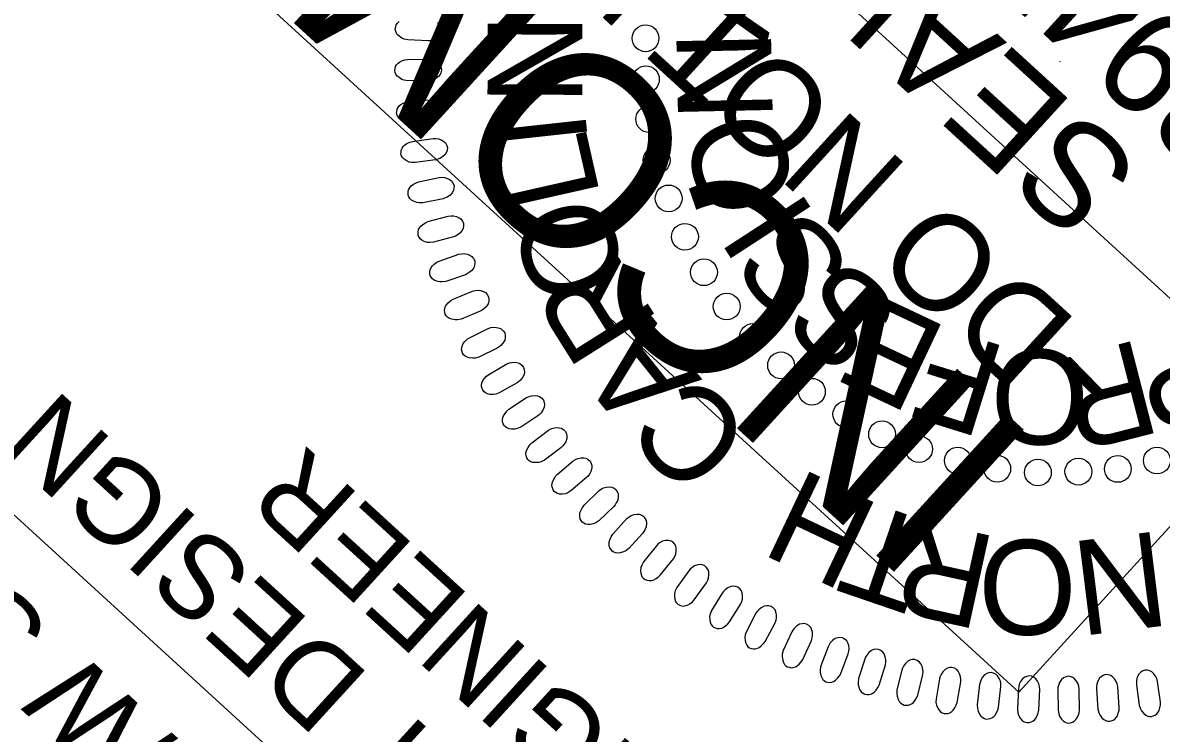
# Model space of a CAD drawing. Extents: x 475722 to 477703, y 499689 to 501633.
# Drawn here: x 475865.2 to 475933.3, y 500762.6 to 500805.1 of the extents above; entities that cross this region are included whole.
import ezdxf

# ---------------------------------------------------------------- set-up
doc = ezdxf.new("R2010")
doc.units = 0
for name, color, linetype in [('Sheet Data Field CELL', 7, 'Continuous'), ('Sheet PE Seal Cell', 7, 'Continuous'), ('Sheet Plan CELL', 7, 'Continuous'), ('Sheet Sticker Incomplete CELL', 7, 'Continuous')]:
    doc.layers.add(name, color=color, linetype=linetype)

msp = doc.modelspace()

# ---------------------------------------------------------------- linework, layer by layer
at = {"layer": 'Sheet PE Seal Cell'}
msp.add_line((475927.242, 500802.785), (475927.274, 500802.82), dxfattribs=at)
msp.add_lwpolyline([(475889.983, 500805.132), (475890.117, 500805.013), (475890.192, 500804.912), (475890.244, 500804.752), (475890.256, 500804.601), (475890.209, 500804.455), (475890.154, 500804.352), (475890.048, 500804.23), (475889.873, 500804.119), (475889.69, 500804.061), (475889.559, 500804.038), (475889.429, 500804.029), (475888.204, 500804.09), (475887.986, 500804.138), (475887.849, 500804.197), (475887.686, 500804.317), (475887.581, 500804.42), (475887.507, 500804.536), (475887.472, 500804.642), (475887.458, 500804.756), (475887.483, 500804.867), (475887.519, 500804.985), (475887.584, 500805.086), (475887.689, 500805.186)], dxfattribs=at)
for points in [[(475889.441, 500801.652), (475888.214, 500801.636), (475887.995, 500801.671), (475887.854, 500801.721), (475887.683, 500801.831), (475887.572, 500801.926), (475887.491, 500802.037), (475887.45, 500802.142), (475887.428, 500802.254), (475887.447, 500802.366), (475887.475, 500802.486), (475887.533, 500802.592), (475887.632, 500802.698), (475887.711, 500802.758), (475887.86, 500802.827), (475888.038, 500802.89), (475888.197, 500802.915), (475889.454, 500802.938), (475889.624, 500802.918), (475889.764, 500802.875), (475889.924, 500802.788), (475890.066, 500802.677), (475890.147, 500802.581), (475890.209, 500802.425), (475890.231, 500802.276), (475890.193, 500802.126), (475890.144, 500802.021), (475890.046, 500801.892), (475889.878, 500801.77), (475889.699, 500801.701), (475889.57, 500801.669)], [(475889.587, 500799.226), (475888.363, 500799.133), (475888.142, 500799.153), (475887.998, 500799.194), (475887.821, 500799.293), (475887.704, 500799.382), (475887.616, 500799.487), (475887.568, 500799.589), (475887.54, 500799.699), (475887.551, 500799.812), (475887.572, 500799.934), (475887.623, 500800.043), (475887.715, 500800.155), (475887.79, 500800.221), (475887.934, 500800.299), (475888.109, 500800.372), (475888.266, 500800.407), (475889.518, 500800.51), (475889.689, 500800.5), (475889.832, 500800.466), (475889.997, 500800.389), (475890.145, 500800.288), (475890.232, 500800.197), (475890.304, 500800.045), (475890.335, 500799.897), (475890.306, 500799.745), (475890.265, 500799.637), (475890.175, 500799.503), (475890.015, 500799.371), (475889.842, 500799.29), (475889.714, 500799.251)], [(475889.873, 500796.913), (475888.658, 500796.743), (475888.436, 500796.749), (475888.29, 500796.782), (475888.106, 500796.869), (475887.985, 500796.95), (475887.89, 500797.051), (475887.836, 500797.148), (475887.801, 500797.257), (475887.805, 500797.37), (475887.818, 500797.493), (475887.863, 500797.605), (475887.947, 500797.723), (475888.018, 500797.793), (475888.157, 500797.88), (475888.326, 500797.964), (475888.481, 500798.009), (475889.724, 500798.19), (475889.896, 500798.192), (475890.04, 500798.166), (475890.21, 500798.1), (475890.365, 500798.008), (475890.457, 500797.923), (475890.538, 500797.776), (475890.578, 500797.63), (475890.56, 500797.477), (475890.525, 500797.366), (475890.443, 500797.227), (475890.292, 500797.085), (475890.123, 500796.993), (475889.999, 500796.946)], [(475890.316, 500794.589), (475889.115, 500794.344), (475888.892, 500794.336), (475888.744, 500794.359), (475888.556, 500794.435), (475888.429, 500794.508), (475888.329, 500794.602), (475888.268, 500794.697), (475888.226, 500794.803), (475888.223, 500794.916), (475888.229, 500795.039), (475888.266, 500795.154), (475888.343, 500795.277), (475888.409, 500795.352), (475888.542, 500795.448), (475888.706, 500795.542), (475888.858, 500795.596), (475890.088, 500795.855), (475890.258, 500795.867), (475890.404, 500795.851), (475890.578, 500795.795), (475890.738, 500795.713), (475890.836, 500795.634), (475890.925, 500795.492), (475890.975, 500795.35), (475890.966, 500795.195), (475890.938, 500795.083), (475890.866, 500794.938), (475890.723, 500794.787), (475890.561, 500794.685), (475890.44, 500794.63)], [(475890.934, 500792.301), (475889.75, 500791.98), (475889.528, 500791.958), (475889.38, 500791.972), (475889.187, 500792.036), (475889.055, 500792.101), (475888.949, 500792.189), (475888.884, 500792.279), (475888.835, 500792.383), (475888.825, 500792.496), (475888.823, 500792.619), (475888.852, 500792.736), (475888.922, 500792.863), (475888.983, 500792.941), (475889.11, 500793.046), (475889.267, 500793.15), (475889.415, 500793.214), (475890.626, 500793.549), (475890.796, 500793.572), (475890.942, 500793.565), (475891.12, 500793.52), (475891.284, 500793.449), (475891.387, 500793.376), (475891.486, 500793.24), (475891.543, 500793.101), (475891.544, 500792.946), (475891.523, 500792.832), (475891.461, 500792.683), (475891.328, 500792.524), (475891.172, 500792.412), (475891.055, 500792.349)], [(475891.654, 500790.037), (475890.492, 500789.643), (475890.273, 500789.608), (475890.124, 500789.612), (475889.927, 500789.664), (475889.792, 500789.721), (475889.68, 500789.801), (475889.609, 500789.888), (475889.554, 500789.987), (475889.537, 500790.1), (475889.527, 500790.223), (475889.549, 500790.341), (475889.61, 500790.472), (475889.667, 500790.554), (475889.786, 500790.666), (475889.937, 500790.781), (475890.081, 500790.854), (475891.269, 500791.264), (475891.436, 500791.298), (475891.583, 500791.3), (475891.763, 500791.267), (475891.931, 500791.205), (475892.038, 500791.139), (475892.145, 500791.01), (475892.212, 500790.875), (475892.223, 500790.72), (475892.209, 500790.605), (475892.155, 500790.452), (475892.033, 500790.285), (475891.885, 500790.163), (475891.771, 500790.093)], [(475892.537, 500787.855), (475891.402, 500787.389), (475891.185, 500787.34), (475891.036, 500787.335), (475890.837, 500787.374), (475890.698, 500787.422), (475890.582, 500787.496), (475890.505, 500787.577), (475890.444, 500787.673), (475890.42, 500787.785), (475890.402, 500787.906), (475890.417, 500788.026), (475890.47, 500788.161), (475890.521, 500788.246), (475890.634, 500788.366), (475890.777, 500788.489), (475890.916, 500788.571), (475892.075, 500789.056), (475892.24, 500789.099), (475892.387, 500789.111), (475892.569, 500789.089), (475892.74, 500789.038), (475892.852, 500788.979), (475892.967, 500788.856), (475893.041, 500788.725), (475893.061, 500788.572), (475893.055, 500788.457), (475893.011, 500788.301), (475892.9, 500788.126), (475892.76, 500787.995), (475892.651, 500787.919)], [(475893.561, 500785.654), (475892.459, 500785.117), (475892.245, 500785.055), (475892.096, 500785.04), (475891.895, 500785.067), (475891.753, 500785.106), (475891.633, 500785.172), (475891.551, 500785.249), (475891.484, 500785.341), (475891.453, 500785.45), (475891.428, 500785.571), (475891.436, 500785.691), (475891.479, 500785.829), (475891.525, 500785.918), (475891.63, 500786.044), (475891.765, 500786.176), (475891.899, 500786.266), (475893.025, 500786.823), (475893.188, 500786.877), (475893.333, 500786.898), (475893.515, 500786.887), (475893.69, 500786.848), (475893.804, 500786.795), (475893.927, 500786.679), (475894.01, 500786.554), (475894.04, 500786.402), (475894.041, 500786.286), (475894.007, 500786.128), (475893.906, 500785.947), (475893.775, 500785.807), (475893.671, 500785.724)], [(475894.751, 500783.571), (475893.684, 500782.966), (475893.474, 500782.89), (475893.328, 500782.867), (475893.124, 500782.88), (475892.981, 500782.911), (475892.857, 500782.969), (475892.77, 500783.04), (475892.698, 500783.128), (475892.66, 500783.236), (475892.627, 500783.355), (475892.627, 500783.475), (475892.662, 500783.615), (475892.702, 500783.706), (475892.799, 500783.839), (475892.926, 500783.979), (475893.053, 500784.078), (475894.143, 500784.704), (475894.301, 500784.769), (475894.445, 500784.798), (475894.628, 500784.799), (475894.805, 500784.77), (475894.922, 500784.725), (475895.052, 500784.618), (475895.143, 500784.497), (475895.182, 500784.348), (475895.19, 500784.233), (475895.166, 500784.073), (475895.078, 500783.885), (475894.955, 500783.738), (475894.856, 500783.648)], [(475895.992, 500781.594), (475894.966, 500780.923), (475894.762, 500780.834), (475894.616, 500780.802), (475894.412, 500780.803), (475894.268, 500780.824), (475894.14, 500780.874), (475894.049, 500780.94), (475893.97, 500781.023), (475893.926, 500781.128), (475893.886, 500781.244), (475893.879, 500781.365), (475893.905, 500781.506), (475893.939, 500781.6), (475894.028, 500781.739), (475894.145, 500781.887), (475894.266, 500781.994), (475895.315, 500782.687), (475895.469, 500782.76), (475895.61, 500782.799), (475895.792, 500782.811), (475895.971, 500782.794), (475896.091, 500782.757), (475896.227, 500782.658), (475896.325, 500782.543), (475896.373, 500782.396), (475896.389, 500782.282), (475896.375, 500782.121), (475896.299, 500781.928), (475896.185, 500781.773), (475896.093, 500781.678)], [(475897.375, 500779.689), (475896.392, 500778.955), (475896.194, 500778.854), (475896.051, 500778.812), (475895.848, 500778.801), (475895.702, 500778.813), (475895.571, 500778.855), (475895.476, 500778.915), (475895.393, 500778.993), (475895.342, 500779.094), (475895.294, 500779.208), (475895.28, 500779.328), (475895.297, 500779.471), (475895.325, 500779.567), (475895.405, 500779.71), (475895.512, 500779.866), (475895.627, 500779.98), (475896.629, 500780.738), (475896.779, 500780.82), (475896.917, 500780.868), (475897.099, 500780.892), (475897.278, 500780.886), (475897.4, 500780.856), (475897.542, 500780.766), (475897.647, 500780.658), (475897.705, 500780.514), (475897.727, 500780.401), (475897.723, 500780.239), (475897.659, 500780.042), (475897.556, 500779.881), (475897.469, 500779.779)], [(475898.908, 500777.9), (475897.974, 500777.105), (475897.782, 500776.991), (475897.642, 500776.941), (475897.44, 500776.917), (475897.293, 500776.92), (475897.16, 500776.954), (475897.062, 500777.007), (475896.974, 500777.08), (475896.917, 500777.179), (475896.863, 500777.289), (475896.84, 500777.407), (475896.849, 500777.552), (475896.87, 500777.649), (475896.941, 500777.798), (475897.039, 500777.959), (475897.146, 500778.079), (475898.099, 500778.899), (475898.243, 500778.991), (475898.377, 500779.048), (475898.557, 500779.083), (475898.736, 500779.088), (475898.86, 500779.066), (475899.007, 500778.984), (475899.12, 500778.884), (475899.186, 500778.744), (475899.216, 500778.632), (475899.222, 500778.47), (475899.17, 500778.269), (475899.077, 500778.102), (475898.997, 500777.995)], [(475900.534, 500776.177), (475899.651, 500775.325), (475899.468, 500775.199), (475899.331, 500775.141), (475899.131, 500775.104), (475898.984, 500775.097), (475898.849, 500775.123), (475898.748, 500775.171), (475898.655, 500775.238), (475898.592, 500775.332), (475898.531, 500775.439), (475898.501, 500775.556), (475898.5, 500775.7), (475898.516, 500775.798), (475898.577, 500775.951), (475898.665, 500776.118), (475898.763, 500776.245), (475899.664, 500777.123), (475899.801, 500777.225), (475899.933, 500777.289), (475900.11, 500777.335), (475900.288, 500777.352), (475900.413, 500777.337), (475900.565, 500777.266), (475900.683, 500777.172), (475900.758, 500777.037), (475900.795, 500776.926), (475900.811, 500776.766), (475900.772, 500776.562), (475900.69, 500776.389), (475900.617, 500776.277)], [(475902.258, 500774.566), (475901.43, 500773.661), (475901.255, 500773.524), (475901.121, 500773.456), (475900.925, 500773.407), (475900.779, 500773.391), (475900.642, 500773.408), (475900.538, 500773.449), (475900.442, 500773.51), (475900.373, 500773.601), (475900.304, 500773.703), (475900.268, 500773.818), (475900.258, 500773.962), (475900.268, 500774.062), (475900.319, 500774.217), (475900.396, 500774.391), (475900.487, 500774.523), (475901.329, 500775.455), (475901.46, 500775.566), (475901.588, 500775.638), (475901.761, 500775.695), (475901.939, 500775.723), (475902.064, 500775.716), (475902.22, 500775.654), (475902.344, 500775.568), (475902.427, 500775.438), (475902.471, 500775.331), (475902.498, 500775.171), (475902.471, 500774.965), (475902.4, 500774.787), (475902.334, 500774.672)], [(475903.087, 500773.82), (475902.318, 500772.865), (475902.21, 500772.67), (475902.163, 500772.529), (475902.144, 500772.326), (475902.151, 500772.18), (475902.188, 500772.047), (475902.244, 500771.951), (475902.32, 500771.865), (475902.419, 500771.81), (475902.531, 500771.759), (475902.65, 500771.739), (475902.794, 500771.752), (475902.891, 500771.776), (475903.037, 500771.85), (475903.196, 500771.953), (475903.313, 500772.063), (475904.107, 500773.037), (475904.196, 500773.183), (475904.249, 500773.32), (475904.28, 500773.501), (475904.279, 500773.68), (475904.254, 500773.803), (475904.169, 500773.948), (475904.065, 500774.057), (475903.923, 500774.12), (475903.811, 500774.147), (475903.649, 500774.148), (475903.45, 500774.092), (475903.285, 500773.994), (475903.18, 500773.912)], [(475905.024, 500772.325), (475904.316, 500771.323), (475904.22, 500771.122), (475904.182, 500770.978), (475904.176, 500770.775), (475904.192, 500770.629), (475904.238, 500770.5), (475904.3, 500770.406), (475904.38, 500770.325), (475904.484, 500770.277), (475904.598, 500770.233), (475904.718, 500770.221), (475904.861, 500770.242), (475904.956, 500770.273), (475905.098, 500770.356), (475905.25, 500770.468), (475905.36, 500770.585), (475906.091, 500771.608), (475906.171, 500771.759), (475906.215, 500771.899), (475906.234, 500772.081), (475906.223, 500772.26), (475906.189, 500772.381), (475906.096, 500772.521), (475905.985, 500772.623), (475905.84, 500772.677), (475905.726, 500772.696), (475905.564, 500772.688), (475905.369, 500772.619), (475905.211, 500772.511), (475905.112, 500772.422)], [(475907.03, 500770.99), (475906.387, 500769.947), (475906.304, 500769.74), (475906.274, 500769.593), (475906.281, 500769.39), (475906.306, 500769.246), (475906.36, 500769.119), (475906.428, 500769.031), (475906.513, 500768.954), (475906.619, 500768.913), (475906.737, 500768.876), (475906.857, 500768.871), (475906.999, 500768.901), (475907.092, 500768.938), (475907.227, 500769.03), (475907.372, 500769.151), (475907.475, 500769.276), (475908.14, 500770.342), (475908.21, 500770.498), (475908.246, 500770.64), (475908.253, 500770.823), (475908.23, 500771.001), (475908.19, 500771.12), (475908.087, 500771.253), (475907.97, 500771.348), (475907.822, 500771.393), (475907.707, 500771.405), (475907.547, 500771.387), (475907.356, 500771.306), (475907.204, 500771.188), (475907.111, 500771.093)], [(475909.051, 500769.784), (475908.474, 500768.701), (475908.404, 500768.49), (475908.384, 500768.342), (475908.404, 500768.14), (475908.438, 500767.998), (475908.499, 500767.874), (475908.573, 500767.789), (475908.662, 500767.719), (475908.771, 500767.684), (475908.89, 500767.655), (475909.011, 500767.658), (475909.15, 500767.697), (475909.24, 500767.739), (475909.37, 500767.84), (475909.507, 500767.97), (475909.602, 500768.1), (475910.199, 500769.206), (475910.259, 500769.366), (475910.285, 500769.51), (475910.281, 500769.693), (475910.248, 500769.869), (475910.199, 500769.985), (475910.089, 500770.113), (475909.966, 500770.2), (475909.816, 500770.235), (475909.7, 500770.241), (475909.541, 500770.212), (475909.356, 500770.118), (475909.212, 500769.992), (475909.125, 500769.892)], [(475911.192, 500768.668), (475910.685, 500767.551), (475910.627, 500767.336), (475910.617, 500767.188), (475910.649, 500766.987), (475910.692, 500766.846), (475910.761, 500766.728), (475910.84, 500766.648), (475910.934, 500766.583), (475911.044, 500766.554), (475911.165, 500766.533), (475911.285, 500766.544), (475911.422, 500766.591), (475911.51, 500766.639), (475911.633, 500766.748), (475911.762, 500766.886), (475911.848, 500767.023), (475912.375, 500768.163), (475912.424, 500768.327), (475912.441, 500768.472), (475912.426, 500768.655), (475912.381, 500768.828), (475912.326, 500768.941), (475912.208, 500769.061), (475912.08, 500769.141), (475911.927, 500769.166), (475911.811, 500769.164), (475911.654, 500769.126), (475911.475, 500769.021), (475911.34, 500768.885), (475911.259, 500768.78)], [(475913.367, 500767.786), (475912.931, 500766.639), (475912.888, 500766.421), (475912.887, 500766.272), (475912.931, 500766.074), (475912.983, 500765.937), (475913.06, 500765.822), (475913.143, 500765.748), (475913.241, 500765.69), (475913.353, 500765.668), (475913.475, 500765.653), (475913.594, 500765.672), (475913.728, 500765.728), (475913.812, 500765.781), (475913.928, 500765.897), (475914.048, 500766.044), (475914.125, 500766.185), (475914.579, 500767.357), (475914.619, 500767.523), (475914.626, 500767.669), (475914.6, 500767.851), (475914.545, 500768.021), (475914.482, 500768.13), (475914.357, 500768.242), (475914.224, 500768.314), (475914.07, 500768.329), (475913.955, 500768.32), (475913.8, 500768.272), (475913.628, 500768.157), (475913.501, 500768.012), (475913.427, 500767.902)], [(475915.56, 500767.046), (475915.196, 500765.875), (475915.167, 500765.655), (475915.175, 500765.505), (475915.231, 500765.31), (475915.293, 500765.177), (475915.376, 500765.067), (475915.464, 500764.998), (475915.565, 500764.946), (475915.678, 500764.932), (475915.801, 500764.925), (475915.919, 500764.951), (475916.049, 500765.015), (475916.129, 500765.074), (475916.238, 500765.196), (475916.348, 500765.35), (475916.417, 500765.496), (475916.796, 500766.694), (475916.825, 500766.863), (475916.824, 500767.009), (475916.785, 500767.188), (475916.719, 500767.355), (475916.651, 500767.459), (475916.518, 500767.563), (475916.381, 500767.627), (475916.227, 500767.633), (475916.112, 500767.616), (475915.961, 500767.559), (475915.797, 500767.433), (475915.679, 500767.281), (475915.612, 500767.166)], [(475917.782, 500766.39), (475917.492, 500765.197), (475917.477, 500764.975), (475917.494, 500764.828), (475917.563, 500764.636), (475917.632, 500764.507), (475917.722, 500764.403), (475917.814, 500764.34), (475917.919, 500764.293), (475918.032, 500764.286), (475918.156, 500764.287), (475918.271, 500764.321), (475918.397, 500764.393), (475918.474, 500764.457), (475918.574, 500764.586), (475918.675, 500764.747), (475918.734, 500764.896), (475919.038, 500766.116), (475919.056, 500766.285), (475919.045, 500766.432), (475918.996, 500766.607), (475918.92, 500766.77), (475918.844, 500766.871), (475918.706, 500766.966), (475918.565, 500767.02), (475918.41, 500767.017), (475918.297, 500766.993), (475918.15, 500766.926), (475917.994, 500766.789), (475917.886, 500766.631), (475917.826, 500766.512)], [(475920.041, 500765.872), (475919.827, 500764.664), (475919.826, 500764.441), (475919.853, 500764.295), (475919.933, 500764.108), (475920.01, 500763.983), (475920.106, 500763.886), (475920.203, 500763.828), (475920.31, 500763.789), (475920.424, 500763.788), (475920.546, 500763.797), (475920.66, 500763.838), (475920.78, 500763.918), (475920.853, 500763.986), (475920.946, 500764.122), (475921.035, 500764.288), (475921.086, 500764.441), (475921.312, 500765.678), (475921.32, 500765.848), (475921.3, 500765.994), (475921.239, 500766.166), (475921.153, 500766.323), (475921.072, 500766.419), (475920.927, 500766.505), (475920.784, 500766.551), (475920.629, 500766.538), (475920.517, 500766.506), (475920.375, 500766.431), (475920.228, 500766.284), (475920.13, 500766.119), (475920.078, 500765.997)], [(475922.432, 500765.523), (475922.294, 500764.303), (475922.307, 500764.081), (475922.343, 500763.937), (475922.435, 500763.755), (475922.52, 500763.636), (475922.622, 500763.544), (475922.722, 500763.492), (475922.831, 500763.46), (475922.944, 500763.467), (475923.066, 500763.483), (475923.177, 500763.531), (475923.293, 500763.619), (475923.361, 500763.691), (475923.445, 500763.833), (475923.524, 500764.004), (475923.564, 500764.16), (475923.713, 500765.408), (475923.709, 500765.579), (475923.681, 500765.723), (475923.61, 500765.891), (475923.514, 500766.042), (475923.426, 500766.133), (475923.277, 500766.21), (475923.13, 500766.246), (475922.977, 500766.223), (475922.868, 500766.186), (475922.73, 500766.101), (475922.592, 500765.946), (475922.505, 500765.775), (475922.461, 500765.649)], [(475924.757, 500765.279), (475924.696, 500764.054), (475924.723, 500763.833), (475924.768, 500763.691), (475924.871, 500763.516), (475924.963, 500763.402), (475925.071, 500763.316), (475925.174, 500763.272), (475925.285, 500763.246), (475925.398, 500763.261), (475925.519, 500763.285), (475925.626, 500763.339), (475925.736, 500763.434), (475925.799, 500763.51), (475925.874, 500763.657), (475925.943, 500763.832), (475925.973, 500763.991), (475926.043, 500765.245), (475926.029, 500765.416), (475925.991, 500765.558), (475925.909, 500765.721), (475925.804, 500765.866), (475925.711, 500765.951), (475925.557, 500766.019), (475925.408, 500766.046), (475925.257, 500766.013), (475925.151, 500765.969), (475925.019, 500765.876), (475924.891, 500765.712), (475924.815, 500765.536), (475924.779, 500765.408)], [(475927.115, 500765.21), (475927.131, 500763.983), (475927.171, 500763.764), (475927.225, 500763.625), (475927.34, 500763.457), (475927.438, 500763.349), (475927.551, 500763.27), (475927.657, 500763.232), (475927.769, 500763.213), (475927.881, 500763.235), (475928, 500763.266), (475928.104, 500763.327), (475928.207, 500763.429), (475928.266, 500763.509), (475928.331, 500763.66), (475928.389, 500763.84), (475928.409, 500763.999), (475928.4, 500765.256), (475928.375, 500765.426), (475928.328, 500765.564), (475928.237, 500765.723), (475928.122, 500765.862), (475928.025, 500765.94), (475927.867, 500765.997), (475927.717, 500766.015), (475927.568, 500765.973), (475927.464, 500765.922), (475927.338, 500765.821), (475927.221, 500765.65), (475927.156, 500765.469), (475927.128, 500765.339)], [(475929.427, 500765.276), (475929.521, 500764.053), (475929.575, 500763.837), (475929.637, 500763.702), (475929.762, 500763.541), (475929.867, 500763.439), (475929.985, 500763.368), (475930.092, 500763.337), (475930.206, 500763.325), (475930.316, 500763.353), (475930.433, 500763.393), (475930.533, 500763.46), (475930.63, 500763.567), (475930.683, 500763.652), (475930.74, 500763.806), (475930.785, 500763.989), (475930.796, 500764.15), (475930.707, 500765.404), (475930.672, 500765.571), (475930.617, 500765.707), (475930.515, 500765.859), (475930.393, 500765.99), (475930.29, 500766.062), (475930.129, 500766.11), (475929.978, 500766.118), (475929.832, 500766.067), (475929.732, 500766.01), (475929.612, 500765.9), (475929.506, 500765.722), (475929.452, 500765.538), (475929.433, 500765.407)], [(475931.824, 500765.507), (475931.993, 500764.292), (475932.061, 500764.08), (475932.132, 500763.949), (475932.267, 500763.796), (475932.378, 500763.701), (475932.5, 500763.638), (475932.609, 500763.613), (475932.723, 500763.609), (475932.832, 500763.644), (475932.946, 500763.691), (475933.041, 500763.764), (475933.131, 500763.877), (475933.179, 500763.965), (475933.225, 500764.122), (475933.26, 500764.309), (475933.26, 500764.469), (475933.093, 500765.715), (475933.047, 500765.88), (475932.983, 500766.011), (475932.872, 500766.157), (475932.742, 500766.28), (475932.634, 500766.345), (475932.471, 500766.383), (475932.321, 500766.382), (475932.178, 500766.322), (475932.081, 500766.258), (475931.969, 500766.142), (475931.874, 500765.957), (475931.832, 500765.77), (475931.821, 500765.637)]]:
    msp.add_lwpolyline(points, close=True, dxfattribs=at)
for centre in [(475902.44, 500804.183), (475902.464, 500801.731), (475902.655, 500799.344), (475903.103, 500796.883), (475903.824, 500794.604), (475904.8, 500792.309), (475905.937, 500790.189), (475907.297, 500788.136), (475908.871, 500786.319), (475910.554, 500784.618), (475912.4, 500783.038), (475914.461, 500781.693), (475916.6, 500780.493), (475918.81, 500779.606), (475921.131, 500778.922), (475933.055, 500778.924), (475923.492, 500778.437), (475925.927, 500778.208), (475928.348, 500778.261), (475930.709, 500778.423)]:
    msp.add_circle(centre, 0.801, dxfattribs=at)
at = {"layer": 'Sheet Plan CELL'}
msp.add_lwpolyline([(475922.287, 500722.978), (475848.428, 500790.468), (475924.324, 500873.526), (475998.157, 500806.027)], close=True, dxfattribs=at)
at = {"layer": 'Sheet Sticker Incomplete CELL'}
msp.add_lwpolyline([(475940.631, 500782.412), (475924.779, 500765.064), (475816.261, 500864.224), (475832.113, 500881.573)], close=True, dxfattribs=at)

# ---------------------------------------------------------------- texts
at = {"layer": 'Sheet Data Field CELL'}
msp.add_text('R-5861', height=7.5, rotation=137.57997, dxfattribs=at).set_placement((475877.848, 500742.927))
at = {"layer": 'Sheet PE Seal Cell'}
for s, height, rotation, p in [('29470', 6.2363, 137.56133, (475939.95, 500800.365)), ('SEAL', 6.2363, 137.56133, (475932.307, 500796.406)), ('A', 5.669, 75.35062, (475909.674, 500803.802)), ('N', 5.669, 89.74214, (475898.644, 500800.174)), ('N', 5.669, 91.23021, (475910.06, 500799.277)), ('I', 5.669, 96.2315, (475899.018, 500797.908)), ('O', 5.669, 107.10981, (475911.688, 500794.667)), ('L', 5.669, 102.72086, (475899.756, 500794.724)), ('I', 5.669, 122.9894, (475912.682, 500793.526)), ('O', 5.669, 109.21021, (475901.543, 500789.663)), ('S', 5.669, 130.9292, (475915.062, 500790.496)), ('R', 5.669, 122.18893, (475903.283, 500787.186)), ('S', 5.669, 138.86899, (475917.98, 500787.967)), ('E', 5.669, 154.74859, (475920.67, 500786.809)), ('A', 5.669, 128.67828, (475905.852, 500783.762)), ('P', 5.669, 202.38738, (475935.553, 500787.548)), ('F', 5.669, 162.68839, (475924.211, 500785.657)), ('O', 5.669, 178.56798, (475929.057, 500785.481)), ('R', 5.669, 194.44758, (475932.04, 500786.204)), ('C', 5.669, 135.16764, (475909.09, 500780.522)), ('H', 5.669, 154.63571, (475916.639, 500776.175)), ('T', 5.669, 161.12507, (475919.937, 500775.072)), ('R', 5.669, 167.61443, (475923.609, 500774.316)), ('N', 5.669, 187.08249, (475933.221, 500774.722)), ('O', 5.669, 180.59314, (475928.217, 500774.207))]:
    msp.add_text(s, height=height, rotation=rotation, dxfattribs=at).set_placement(p)
at = {"layer": 'Sheet Plan CELL'}
for s, p in [('R/W SHEET NO.', (475877.982, 500758.992)), ('ROADWAY DESIGN', (475912.908, 500741.436)), ('ENGINEER', (475907.667, 500756.436)), ('PROJECT REFERENCE NO.', (475886.437, 500716.655))]:
    msp.add_text(s, height=5.0001, rotation=137.57997, dxfattribs=at).set_placement(p)
at = {"layer": 'Sheet Sticker Incomplete CELL'}
for s, height, p in [('INCOMPLETE PLANS', 11.52, (475926.132, 500779.812)), ('DO NOT USE FOR R/W ACQUISITION', 5.76, (475928.421, 500787.135))]:
    msp.add_text(s, height=height, rotation=137.57996, dxfattribs=at).set_placement(p)

doc.saveas('drawing.dxf')
